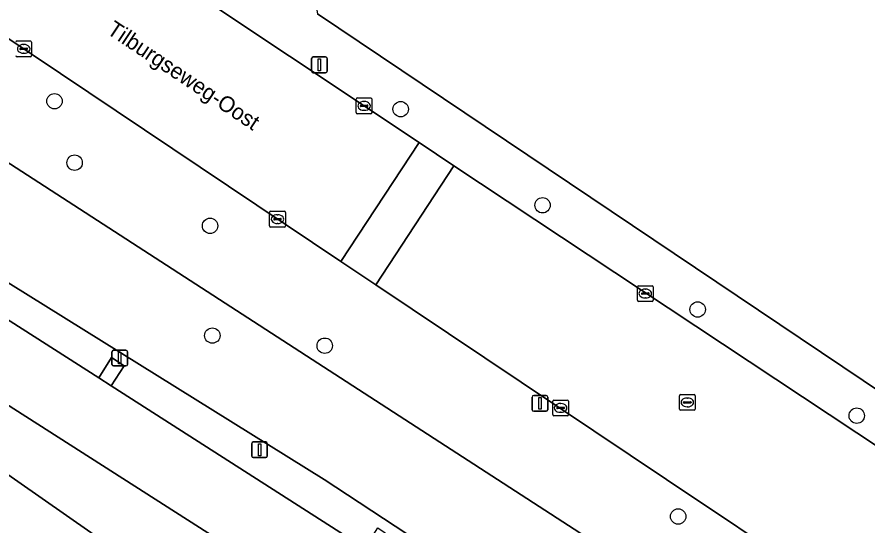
# Model space of a CAD drawing. Extents: x 158352 to 159489, y 383828 to 384603.
# Drawn here: x 158687.8 to 158741.8, y 383997.1 to 384029.4 of the extents above; entities that cross this region are included whole.
import ezdxf

# ---------------------------------------------------------------- set-up
doc = ezdxf.new("R2010")
doc.units = 0
for name, color, linetype in [('IMGEO_Berm_groen', 7, 'Continuous'), ('IMGEO_Boom', 7, 'Continuous'), ('IMGEO_Erf', 7, 'Continuous'), ('IMGEO_Groenvoorziening', 7, 'Continuous'), ('IMGEO_Kolk', 7, 'Continuous'), ('IMGEO_Lichtmast', 7, 'Continuous'), ('IMGEO_Openbare_ruimte_label', 7, 'Continuous'), ('IMGEO_Rijbaan_lokaal_open', 7, 'Continuous'), ('IMGEO_Rijbaan_regionaal_gesloten', 7, 'Continuous'), ('IMGEO_Rioolput', 7, 'Continuous'), ('IMGEO_Voetpad_open', 7, 'Continuous')]:
    doc.layers.add(name, color=color, linetype=linetype)

msp = doc.modelspace()

# ---------------------------------------------------------------- linework, layer by layer
at = {"layer": 'IMGEO_Berm_groen'}
for points in [[(158642.504, 384037.211), (158658.861, 384027.393), (158659.602, 384028.706), (158660.415, 384028.196), (158659.633, 384026.899), (158676.071, 384017.151), (158676.794, 384018.469), (158677.624, 384017.986), (158676.885, 384016.664), (158683.291, 384012.679), (158693.043, 384006.463), (158693.853, 384007.754), (158694.653, 384007.224), (158693.84, 384005.947), (158709.941, 383995.652), (158710.778, 383996.936), (158711.571, 383996.395), (158710.741, 383995.129), (158725.822, 383985.49), (158726.831, 383984.845), (158727.604, 383986.135), (158728.422, 383985.634), (158727.655, 383984.329), (158743.756, 383974.053)], [(158765.871, 383961.56), (158707.358, 384000), (158677.929, 384018.316), (158661.741, 384028.584), (158651.483, 384034.675)], [(158809.311, 383924.969), (158764.39, 383955.088), (158755.227, 383961.2), (158745.974, 383967.224), (158723.089, 383981.844), (158660.628, 384021.748)], [(158659.949, 384021.569), (158658.997, 384020.06), (158719.87, 383977.549), (158722.355, 383976.815), (158737.116, 383966.874), (158761.637, 383950.03), (158810.032, 383915.926), (158827.198, 383905.391), (158846.564, 383892.216), (158863.926, 383878.374), (158875.474, 383869.523), (158882.921, 383862.988), (158886.793, 383863.483), (158886.442, 383864.681), (158887.482, 383869.723), (158884.881, 383873.33), (158882.767, 383874.369), (158883.199, 383875.722), (158882.014, 383876.131)], [(158735.999, 383965.349), (158730.549, 383969.3), (158719.87, 383977.549), (158658.997, 384020.06), (158658.07, 384018.59)]]:
    msp.add_lwpolyline(points, dxfattribs=at)
at = {"layer": 'IMGEO_Boom'}
for centre in [(158690.228, 384024.035), (158712.221, 384023.531), (158691.508, 384020.131), (158721.232, 384017.426), (158700.113, 384016.119), (158731.084, 384010.805), (158700.256, 384009.149), (158707.394, 384008.505), (158741.191, 384004.059), (158729.848, 383997.658)]:
    msp.add_circle(centre, 0.489, dxfattribs=at)
at = {"layer": 'IMGEO_Erf'}
msp.add_lwpolyline([(158778.184, 384060.662), (158706.5, 384047.092), (158707.6, 384041.192), (158704.875, 384040.668), (158706.944, 384029.577), (158750.948, 384000)], dxfattribs=at)
at = {"layer": 'IMGEO_Groenvoorziening'}
msp.add_lwpolyline([(158613.197, 384066.952), (158612.294, 384067.106), (158609.144, 384064.921), (158606.221, 384062.826), (158611.3, 384058.953), (158613.62, 384057.184), (158614.378, 384057.858), (158626.962, 384050.112), (158651.483, 384034.675), (158661.741, 384028.584), (158677.929, 384018.316), (158707.358, 384000), (158765.871, 383961.56), (158795.981, 383941.779), (158809.728, 383931.93), (158811, 383936.053), (158800.948, 383942.61), (158788.302, 383952.844), (158769.011, 383966.352), (158753.016, 383977.553), (158718.365, 384000), (158666.397, 384033.665)], dxfattribs=at)
msp.add_lwpolyline([(158683.45, 384030.599), (158676.121, 384035.659), (158673.761, 384032.455), (158664.976, 384036.523), (158631.002, 384057.298), (158666.397, 384033.665), (158718.365, 384000), (158753.016, 383977.553), (158769.011, 383966.352), (158772.161, 383971.159), (158772.196, 383971.212), (158767.881, 383974.094), (158765.611, 383975.61), (158729.099, 384000), (158710.634, 384012.378), (158708.423, 384013.859)], close=True, dxfattribs=at)
at = {"layer": 'IMGEO_Kolk'}
for p, q in [((158687.848, 384027.86), (158688.7, 384027.86)), ((158688.774, 384027.786), (158688.774, 384026.934)), ((158688.032, 384027.354), (158688.032, 384027.366)), ((158688.47, 384027.317), (158688.072, 384027.317)), ((158688.075, 384027.403), (158688.473, 384027.403)), ((158688.261, 384027.64), (158688.286, 384027.64)), ((158688.516, 384027.366), (158688.516, 384027.354)), ((158688.7, 384026.86), (158687.848, 384026.86)), ((158688.284, 384027.08), (158688.259, 384027.08)), ((158709.397, 384023.313), (158709.397, 384024.165)), ((158709.472, 384024.239), (158710.324, 384024.239)), ((158709.885, 384024.019), (158709.91, 384024.019)), ((158710.398, 384024.165), (158710.398, 384023.313)), ((158709.656, 384023.733), (158709.656, 384023.745)), ((158710.094, 384023.696), (158709.696, 384023.696)), ((158709.699, 384023.782), (158710.097, 384023.782)), ((158709.908, 384023.459), (158709.883, 384023.459)), ((158710.14, 384023.745), (158710.14, 384023.733)), ((158710.324, 384023.239), (158709.472, 384023.239)), ((158703.896, 384016.118), (158703.896, 384016.97)), ((158703.971, 384017.044), (158704.823, 384017.044)), ((158704.897, 384016.97), (158704.897, 384016.118)), ((158704.155, 384016.538), (158704.155, 384016.55)), ((158704.593, 384016.501), (158704.195, 384016.501)), ((158704.198, 384016.587), (158704.596, 384016.587)), ((158704.384, 384016.824), (158704.409, 384016.824)), ((158704.639, 384016.55), (158704.639, 384016.538)), ((158704.823, 384016.044), (158703.971, 384016.044)), ((158704.407, 384016.264), (158704.382, 384016.264)), ((158727.258, 384011.392), (158727.258, 384012.244)), ((158727.333, 384012.318), (158728.185, 384012.318)), ((158727.746, 384012.098), (158727.771, 384012.098)), ((158728.259, 384012.244), (158728.259, 384011.392)), ((158727.517, 384011.812), (158727.517, 384011.824)), ((158727.955, 384011.775), (158727.557, 384011.775)), ((158727.56, 384011.861), (158727.958, 384011.861)), ((158727.769, 384011.538), (158727.744, 384011.538)), ((158728.001, 384011.824), (158728.001, 384011.812)), ((158728.185, 384011.318), (158727.333, 384011.318)), ((158721.953, 384005.053), (158722.805, 384005.053)), ((158721.878, 384004.127), (158721.878, 384004.979)), ((158722.137, 384004.547), (158722.137, 384004.559)), ((158722.575, 384004.51), (158722.177, 384004.51)), ((158722.18, 384004.596), (158722.578, 384004.596)), ((158722.366, 384004.833), (158722.391, 384004.833)), ((158722.621, 384004.559), (158722.621, 384004.547)), ((158722.879, 384004.979), (158722.879, 384004.127)), ((158722.805, 384004.053), (158721.953, 384004.053)), ((158722.389, 384004.273), (158722.364, 384004.273))]:
    msp.add_line(p, q, dxfattribs=at)
for points in [[(158687.848, 384027.86), (158688.7, 384027.86)], [(158688.774, 384027.786), (158688.774, 384026.934)], [(158688.7, 384026.86), (158687.848, 384026.86)], [(158709.397, 384023.313), (158709.397, 384024.165)], [(158709.472, 384024.239), (158710.324, 384024.239)], [(158710.398, 384024.165), (158710.398, 384023.313)], [(158710.324, 384023.239), (158709.472, 384023.239)], [(158703.896, 384016.118), (158703.896, 384016.97)], [(158703.971, 384017.044), (158704.823, 384017.044)], [(158704.897, 384016.97), (158704.897, 384016.118)], [(158704.823, 384016.044), (158703.971, 384016.044)], [(158727.258, 384011.392), (158727.258, 384012.244)], [(158727.333, 384012.318), (158728.185, 384012.318)], [(158728.259, 384012.244), (158728.259, 384011.392)], [(158728.185, 384011.318), (158727.333, 384011.318)], [(158721.953, 384005.053), (158722.805, 384005.053)], [(158721.878, 384004.127), (158721.878, 384004.979)], [(158722.879, 384004.979), (158722.879, 384004.127)], [(158722.805, 384004.053), (158721.953, 384004.053)]]:
    msp.add_lwpolyline(points, dxfattribs=at)
for centre, radius, start, end in [((158687.85, 384027.784), 0.0765, 91.552, 178.448), ((158687.85, 384027.784), 0.0765, 91.552, 178.448), ((158688.698, 384027.784), 0.0765, 1.552, 88.448), ((158688.698, 384027.784), 0.0765, 1.552, 88.448), ((158688.072, 384027.363), 0.0403, 85.8775, 175.7526), ((158688.069, 384027.353), 0.0366, 178.938, 274.7102), ((158688.473, 384027.36), 0.043, 264.8664, 352.4533), ((158688.477, 384027.365), 0.0386, 1.7309, 96.639), ((158687.85, 384026.936), 0.0765, 181.552, 268.448), ((158687.85, 384026.936), 0.0765, 181.552, 268.448), ((158688.698, 384026.936), 0.0765, 271.552, 358.448), ((158688.698, 384026.936), 0.0765, 271.552, 358.448), ((158709.474, 384024.163), 0.0765, 91.552, 178.448), ((158709.474, 384024.163), 0.0765, 91.552, 178.448), ((158710.322, 384024.163), 0.0765, 1.552, 88.448), ((158710.322, 384024.163), 0.0765, 1.552, 88.448), ((158709.696, 384023.742), 0.0403, 85.8775, 175.7526), ((158709.693, 384023.732), 0.0366, 178.938, 274.7102), ((158710.097, 384023.739), 0.043, 264.8664, 352.4533), ((158710.101, 384023.744), 0.0386, 1.7309, 96.639), ((158709.474, 384023.315), 0.0765, 181.552, 268.448), ((158709.474, 384023.315), 0.0765, 181.552, 268.448), ((158710.322, 384023.315), 0.0765, 271.552, 358.448), ((158710.322, 384023.315), 0.0765, 271.552, 358.448), ((158703.973, 384016.968), 0.0765, 91.552, 178.448), ((158703.973, 384016.968), 0.0765, 91.552, 178.448), ((158704.821, 384016.968), 0.0765, 1.552, 88.448), ((158704.821, 384016.968), 0.0765, 1.552, 88.448), ((158704.195, 384016.547), 0.0403, 85.8775, 175.7526), ((158704.192, 384016.537), 0.0366, 178.938, 274.7102), ((158704.596, 384016.544), 0.043, 264.8664, 352.4533), ((158704.6, 384016.549), 0.0386, 1.7309, 96.639), ((158703.973, 384016.12), 0.0765, 181.552, 268.448), ((158703.973, 384016.12), 0.0765, 181.552, 268.448), ((158704.821, 384016.12), 0.0765, 271.552, 358.448), ((158704.821, 384016.12), 0.0765, 271.552, 358.448), ((158727.335, 384012.242), 0.0765, 91.552, 178.448), ((158727.335, 384012.242), 0.0765, 91.552, 178.448), ((158728.183, 384012.242), 0.0765, 1.552, 88.448), ((158728.183, 384012.242), 0.0765, 1.552, 88.448), ((158727.557, 384011.821), 0.0403, 85.8775, 175.7526), ((158727.554, 384011.811), 0.0366, 178.938, 274.7102), ((158727.958, 384011.818), 0.043, 264.8664, 352.4533), ((158727.962, 384011.823), 0.0386, 1.7309, 96.639), ((158727.335, 384011.394), 0.0765, 181.552, 268.448), ((158727.335, 384011.394), 0.0765, 181.552, 268.448), ((158728.183, 384011.394), 0.0765, 271.552, 358.448), ((158728.183, 384011.394), 0.0765, 271.552, 358.448), ((158721.955, 384004.977), 0.0765, 91.552, 178.448), ((158721.955, 384004.977), 0.0765, 91.552, 178.448), ((158722.803, 384004.977), 0.0765, 1.552, 88.448), ((158722.803, 384004.977), 0.0765, 1.552, 88.448), ((158722.177, 384004.556), 0.0403, 85.8775, 175.7526), ((158722.174, 384004.546), 0.0366, 178.938, 274.7102), ((158722.578, 384004.553), 0.043, 264.8664, 352.4533), ((158722.582, 384004.558), 0.0386, 1.7309, 96.639), ((158721.955, 384004.129), 0.0765, 181.552, 268.448), ((158721.955, 384004.129), 0.0765, 181.552, 268.448), ((158722.803, 384004.129), 0.0765, 271.552, 358.448), ((158722.803, 384004.129), 0.0765, 271.552, 358.448)]:
    msp.add_arc(centre, radius, start, end, dxfattribs=at)
for centre, major_axis, ratio, start_param, end_param in [((158688.26, 384027.36), (-0.387, 0.002), 0.722429, 4.712389, 7.853982), ((158688.285, 384027.36), (-0.39, 0.002), 0.717154, 1.570796, 4.712389), ((158709.884, 384023.739), (-0.387, 0.002), 0.722429, 4.712389, 7.853982), ((158709.909, 384023.739), (-0.39, 0.002), 0.717154, 1.570796, 4.712389), ((158704.383, 384016.544), (-0.387, 0.002), 0.722429, 4.712389, 7.853982), ((158704.408, 384016.544), (-0.39, 0.002), 0.717154, 1.570796, 4.712389), ((158727.745, 384011.818), (-0.387, 0.002), 0.722429, 4.712389, 7.853982), ((158727.77, 384011.818), (-0.39, 0.002), 0.717154, 1.570796, 4.712389), ((158722.365, 384004.553), (-0.387, 0.002), 0.722429, 4.712389, 7.853982), ((158722.39, 384004.553), (-0.39, 0.002), 0.717154, 1.570796, 4.712389)]:
    msp.add_ellipse(centre, major_axis=major_axis, ratio=ratio, start_param=start_param, end_param=end_param, dxfattribs=at)
at = {"layer": 'IMGEO_Lichtmast'}
for p, q in [((158706.565, 384025.945), (158706.565, 384026.745)), ((158706.565, 384026.745), (158706.565, 384025.945)), ((158706.665, 384026.845), (158707.455, 384026.845)), ((158707.455, 384026.845), (158706.665, 384026.845)), ((158707.555, 384026.745), (158707.555, 384025.945)), ((158707.555, 384025.945), (158707.555, 384026.745)), ((158707.455, 384025.845), (158706.665, 384025.845)), ((158706.665, 384025.845), (158707.455, 384025.845)), ((158693.88, 384007.318), (158693.88, 384008.118)), ((158693.88, 384008.118), (158693.88, 384007.318)), ((158693.98, 384008.218), (158694.77, 384008.218)), ((158694.77, 384008.218), (158693.98, 384008.218)), ((158694.87, 384008.118), (158694.87, 384007.318)), ((158694.87, 384007.318), (158694.87, 384008.118)), ((158694.77, 384007.218), (158693.98, 384007.218)), ((158693.98, 384007.218), (158694.77, 384007.218)), ((158720.568, 384004.441), (158720.568, 384005.241)), ((158720.568, 384005.241), (158720.568, 384004.441)), ((158720.668, 384005.341), (158721.458, 384005.341)), ((158721.458, 384005.341), (158720.668, 384005.341)), ((158721.558, 384005.241), (158721.558, 384004.441)), ((158721.558, 384004.441), (158721.558, 384005.241)), ((158721.458, 384004.341), (158720.668, 384004.341)), ((158720.668, 384004.341), (158721.458, 384004.341)), ((158702.858, 384002.394), (158703.648, 384002.394)), ((158703.648, 384002.394), (158702.858, 384002.394)), ((158702.758, 384001.494), (158702.758, 384002.294)), ((158702.758, 384002.294), (158702.758, 384001.494)), ((158703.748, 384002.294), (158703.748, 384001.494)), ((158703.748, 384001.494), (158703.748, 384002.294)), ((158703.648, 384001.394), (158702.858, 384001.394)), ((158702.858, 384001.394), (158703.648, 384001.394))]:
    msp.add_line(p, q, dxfattribs=at)
for points in [[(158706.985, 384026.72), (158707.135, 384026.72), (158707.135, 384025.97), (158706.985, 384025.97), (158706.985, 384026.72)], [(158694.3, 384008.093), (158694.45, 384008.093), (158694.45, 384007.343), (158694.3, 384007.343), (158694.3, 384008.093)], [(158720.988, 384005.216), (158721.138, 384005.216), (158721.138, 384004.466), (158720.988, 384004.466), (158720.988, 384005.216)], [(158703.178, 384002.269), (158703.328, 384002.269), (158703.328, 384001.519), (158703.178, 384001.519), (158703.178, 384002.269)]]:
    msp.add_lwpolyline(points, dxfattribs=at)
for centre, start, end in [((158706.665, 384026.745), 90, 180), ((158706.665, 384026.745), 90, 180), ((158707.455, 384026.745), 0, 90), ((158707.455, 384026.745), 360, 90), ((158706.665, 384025.945), 180, 270), ((158706.665, 384025.945), 180, 270), ((158707.455, 384025.945), 270, 0), ((158707.455, 384025.945), 270, 0), ((158693.98, 384008.118), 90, 180), ((158693.98, 384008.118), 90, 180), ((158694.77, 384008.118), 0, 90), ((158694.77, 384008.118), 360, 90), ((158693.98, 384007.318), 180, 270), ((158693.98, 384007.318), 180, 270), ((158694.77, 384007.318), 270, 0), ((158694.77, 384007.318), 270, 0), ((158720.668, 384005.241), 90, 180), ((158720.668, 384005.241), 90, 180), ((158721.458, 384005.241), 0, 90), ((158721.458, 384005.241), 360, 90), ((158720.668, 384004.441), 180, 270), ((158720.668, 384004.441), 180, 270), ((158721.458, 384004.441), 270, 0), ((158721.458, 384004.441), 270, 0), ((158702.858, 384002.294), 90, 180), ((158702.858, 384002.294), 90, 180), ((158703.648, 384002.294), 0, 90), ((158703.648, 384002.294), 360, 90), ((158702.858, 384001.494), 180, 270), ((158702.858, 384001.494), 180, 270), ((158703.648, 384001.494), 270, 0), ((158703.648, 384001.494), 270, 0)]:
    msp.add_arc(centre, 0.1, start, end, dxfattribs=at)
at = {"layer": 'IMGEO_Rijbaan_lokaal_open'}
msp.add_lwpolyline([(158673.127, 384037.94), (158676.121, 384035.659), (158683.45, 384030.599), (158708.423, 384013.859), (158713.384, 384021.411), (158688.754, 384037.85)], dxfattribs=at)
for points in [[(158710.634, 384012.378), (158715.596, 384019.935), (158713.384, 384021.411), (158708.423, 384013.859)], [(158710.634, 384012.378), (158729.099, 384000), (158765.611, 383975.61), (158770.642, 383983.042), (158767.638, 383985.057), (158747.04, 383999.013), (158744.584, 384000.725), (158715.596, 384019.935)], [(158694.653, 384007.224), (158693.853, 384007.754), (158693.043, 384006.463), (158693.84, 384005.947)]]:
    msp.add_lwpolyline(points, close=True, dxfattribs=at)
at = {"layer": 'IMGEO_Rijbaan_regionaal_gesloten'}
for points in [[(158743.756, 383974.053), (158727.655, 383984.329), (158726.831, 383984.845), (158725.822, 383985.49), (158710.741, 383995.129), (158709.941, 383995.652), (158693.84, 384005.947), (158693.043, 384006.463), (158683.291, 384012.679), (158676.885, 384016.664), (158676.071, 384017.151), (158659.633, 384026.899), (158658.861, 384027.393), (158642.504, 384037.211), (158641.681, 384037.738), (158625.433, 384047.682), (158624.607, 384048.204), (158618.011, 384052.527), (158652.865, 384026.773), (158659.949, 384021.569)], [(158660.628, 384021.748), (158723.089, 383981.844), (158745.974, 383967.224), (158755.227, 383961.2), (158764.39, 383955.088), (158809.311, 383924.969)]]:
    msp.add_lwpolyline(points, dxfattribs=at)
at = {"layer": 'IMGEO_Rioolput'}
for p, q in [((158729.927, 384004.476), (158729.927, 384005.328)), ((158730.002, 384005.402), (158730.854, 384005.402)), ((158730.415, 384005.182), (158730.44, 384005.182)), ((158730.928, 384005.328), (158730.928, 384004.476)), ((158730.186, 384004.896), (158730.186, 384004.908)), ((158730.624, 384004.859), (158730.226, 384004.859)), ((158730.229, 384004.945), (158730.627, 384004.945)), ((158730.438, 384004.622), (158730.413, 384004.622)), ((158730.67, 384004.908), (158730.67, 384004.896)), ((158730.854, 384004.402), (158730.002, 384004.402))]:
    msp.add_line(p, q, dxfattribs=at)
for points in [[(158729.927, 384004.476), (158729.927, 384005.328)], [(158730.002, 384005.402), (158730.854, 384005.402)], [(158730.928, 384005.328), (158730.928, 384004.476)], [(158730.854, 384004.402), (158730.002, 384004.402)]]:
    msp.add_lwpolyline(points, dxfattribs=at)
for centre, radius, start, end in [((158730.004, 384005.326), 0.0765, 91.552, 178.448), ((158730.004, 384005.326), 0.0765, 91.552, 178.448), ((158730.852, 384005.326), 0.0765, 1.552, 88.448), ((158730.852, 384005.326), 0.0765, 1.552, 88.448), ((158730.004, 384004.478), 0.0765, 181.552, 268.448), ((158730.004, 384004.478), 0.0765, 181.552, 268.448), ((158730.226, 384004.905), 0.0403, 85.8775, 175.7526), ((158730.223, 384004.895), 0.0366, 178.938, 274.7102), ((158730.627, 384004.902), 0.043, 264.8664, 352.4533), ((158730.631, 384004.907), 0.0386, 1.7309, 96.639), ((158730.852, 384004.478), 0.0765, 271.552, 358.448), ((158730.852, 384004.478), 0.0765, 271.552, 358.448)]:
    msp.add_arc(centre, radius, start, end, dxfattribs=at)
for centre, major_axis, ratio, start_param, end_param in [((158730.414, 384004.902), (-0.387, 0.002), 0.722429, 4.712389, 7.853982), ((158730.439, 384004.902), (-0.39, 0.002), 0.717154, 1.570796, 4.712389)]:
    msp.add_ellipse(centre, major_axis=major_axis, ratio=ratio, start_param=start_param, end_param=end_param, dxfattribs=at)
at = {"layer": 'IMGEO_Voetpad_open'}
for points in [[(158688.754, 384037.85), (158713.384, 384021.411), (158715.596, 384019.935), (158744.584, 384000.725), (158747.04, 383999.013), (158767.638, 383985.057), (158770.642, 383983.042), (158772.851, 383981.561), (158797.412, 383965.088)], [(158802.556, 383964.372), (158800.049, 383966.997), (158760.865, 383993.334), (158759.062, 383994.546), (158750.948, 384000), (158706.944, 384029.577)]]:
    msp.add_lwpolyline(points, dxfattribs=at)

# ---------------------------------------------------------------- texts
at = {"layer": 'IMGEO_Openbare_ruimte_label'}
msp.add_text('Tilburgseweg-Oost', height=1, rotation=326.294, dxfattribs=at).set_placement((158693.492, 384028.376))

doc.saveas('drawing.dxf')
